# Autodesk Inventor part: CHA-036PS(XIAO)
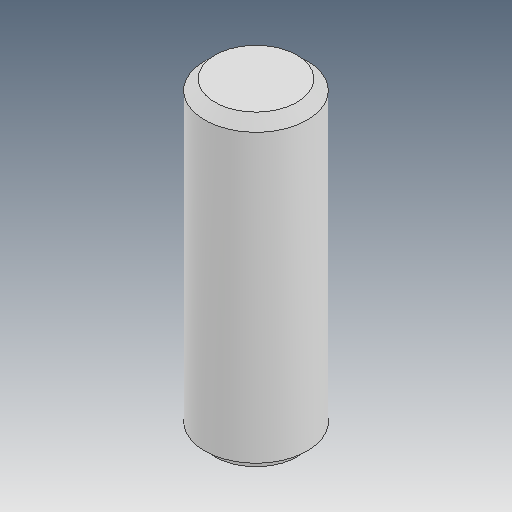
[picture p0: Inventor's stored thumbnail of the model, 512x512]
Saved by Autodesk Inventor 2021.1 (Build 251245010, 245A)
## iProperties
Created: 2021-05
Part Number: CHA-036PS(XIAO)
Material: Ogólny
Document SubType Name: Modeling
Designer: user
Density: 1 g/cm^3
Appearance: Domyślna
Author: user
Revision Number: ÈÎºÎ
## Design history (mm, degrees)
feature "µ¹½Ç1"
node "Bryła1"
